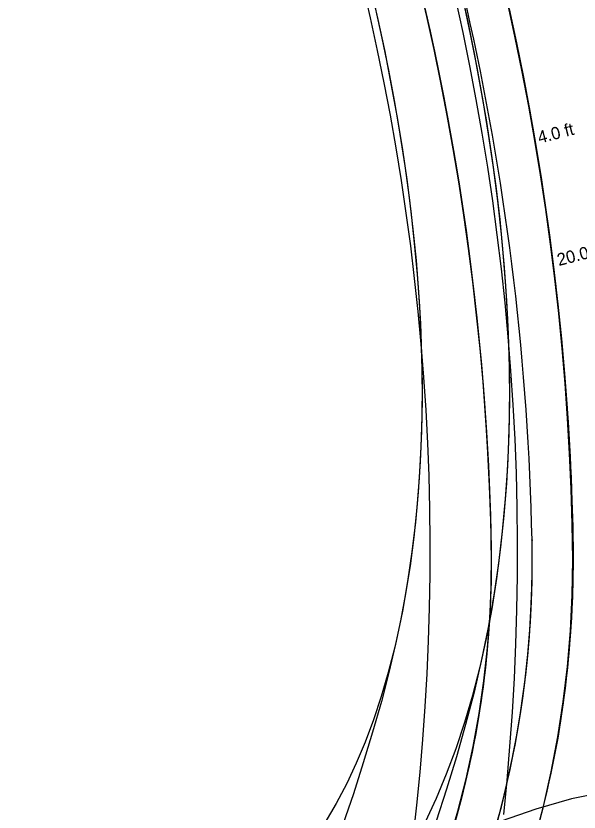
# Model space of a CAD drawing. Extents: x 916040 to 917457, y 328936 to 330267.
# Drawn here: x 916599.7 to 916654.5, y 329738.6 to 329816 of the extents above; entities that cross this region are included whole.
import ezdxf

# ---------------------------------------------------------------- set-up
doc = ezdxf.new("R2010")
doc.units = 0
for name, color, linetype in [('EB_LeftontoManchester_WB67', 7, 'Continuous'), ('EB_LeftontoManchester_WB67_v2', 7, 'Continuous'), ('NB_ThruontoManchester_WB67', 7, 'Continuous'), ('SB_LeftontoRoute25_WB67', 7, 'Continuous'), ('SB_RightontoRoute25_WB67_v2', 7, 'Continuous'), ('SB_ThruontonSacoRd_WB67', 7, 'Continuous'), ('SU_IntoDriveway', 7, 'Continuous'), ('WB_LeftontoSaco_WB67', 7, 'Continuous'), ('WB_RightontoManchester_WB67', 7, 'Continuous')]:
    doc.layers.add(name, color=color, linetype=linetype)

msp = doc.modelspace()

# ---------------------------------------------------------------- linework, layer by layer
at = {"layer": 'EB_LeftontoManchester_WB67'}
msp.add_arc((916291.649, 329706.552), 388, 12.26429, 55.55708, dxfattribs=at)
at = {"layer": 'EB_LeftontoManchester_WB67_v2'}
msp.add_arc((916291.649, 329706.552), 388, 12.26429, 55.55708, dxfattribs=at)
at = {"layer": 'NB_ThruontoManchester_WB67'}
msp.add_arc((916291.649, 329706.552), 388, 11.6689, 55.55708, dxfattribs=at)
at = {"layer": 'SB_LeftontoRoute25_WB67'}
for points in [[(916634.227, 329818.8), (916634.934, 329815.67), (916635.596, 329812.544), (916636.209, 329809.423), (916636.773, 329806.308), (916637.284, 329803.201), (916637.74, 329800.101), (916638.14, 329797.009), (916638.481, 329793.927), (916638.761, 329790.855), (916638.978, 329787.794), (916639.13, 329784.744), (916639.215, 329781.707), (916639.233, 329778.672), (916639.181, 329775.66), (916639.057, 329772.672), (916638.86, 329769.712), (916638.59, 329766.782), (916638.245, 329763.882), (916637.824, 329761.016), (916637.318, 329758.133), (916636.722, 329755.223), (916636.038, 329752.29), (916635.271, 329749.337), (916634.427, 329746.365), (916633.516, 329743.378), (916632.546, 329740.379), (916631.531, 329737.37)], [(916639.282, 329817.724), (916640.011, 329814.521), (916640.699, 329811.309), (916641.345, 329808.089), (916641.949, 329804.861), (916642.512, 329801.625), (916643.033, 329798.382), (916643.512, 329795.133), (916643.949, 329791.879), (916644.344, 329788.619), (916644.697, 329785.354), (916645.008, 329782.084), (916645.276, 329778.812), (916645.503, 329775.536), (916645.687, 329772.257), (916645.828, 329768.976), (916645.928, 329765.694), (916645.967, 329762.417), (916645.894, 329759.151), (916645.706, 329755.899), (916645.404, 329752.662), (916644.99, 329749.444), (916644.463, 329746.247), (916643.825, 329743.075), (916643.077, 329739.931), (916642.219, 329736.817)], [(916643.236, 329817.493), (916643.923, 329814.251), (916644.56, 329811.007), (916645.148, 329807.763), (916645.681, 329804.518), (916646.159, 329801.274), (916646.579, 329798.03), (916646.937, 329794.789), (916647.232, 329791.551), (916647.461, 329788.316), (916647.623, 329785.086), (916647.714, 329781.863), (916647.733, 329778.634), (916647.677, 329775.421), (916647.545, 329772.227), (916647.335, 329769.053), (916647.045, 329765.902), (916646.673, 329762.776), (916646.218, 329759.676), (916645.67, 329756.556), (916645.027, 329753.415), (916644.293, 329750.264), (916643.475, 329747.113), (916642.582, 329743.968), (916641.626, 329740.833), (916640.618, 329737.713)], [(916647.705, 329816.696), (916648.42, 329813.387), (916649.092, 329810.068), (916649.721, 329806.741), (916650.307, 329803.406), (916650.85, 329800.064), (916651.35, 329796.714), (916651.807, 329793.359), (916652.22, 329789.998), (916652.59, 329786.632), (916652.917, 329783.261), (916653.2, 329779.886), (916653.439, 329776.508), (916653.635, 329773.127), (916653.787, 329769.744), (916653.896, 329766.359), (916653.943, 329762.946), (916653.877, 329759.513), (916653.693, 329756.076), (916653.391, 329752.64), (916652.971, 329749.21), (916652.433, 329745.792), (916651.776, 329742.391), (916651.003, 329739.01), (916650.113, 329735.655)]]:
    msp.add_lwpolyline(points, dxfattribs=at)
msp.add_circle((916649.935, 329765.025), 0.0417, dxfattribs=at)
msp.add_circle((916649.935, 329765.025), 0.0417, dxfattribs=at)
for centre, radius, start, end in [((916391.491, 329759.636), 258.5, 1.1947, 23.66768), ((916553.456, 329763.013), 96.5, 331.95112, 1.1947)]:
    msp.add_arc(centre, radius, start, end, dxfattribs=at)
at = {"layer": 'SB_RightontoRoute25_WB67_v2'}
for points in [[(916638.979, 329819.002), (916639.724, 329815.803), (916640.429, 329812.595), (916641.091, 329809.378), (916641.712, 329806.153), (916642.292, 329802.92), (916642.83, 329799.68), (916643.325, 329796.434), (916643.779, 329793.181), (916644.191, 329789.923), (916644.561, 329786.66), (916644.889, 329783.393), (916645.174, 329780.121), (916645.417, 329776.846), (916645.618, 329773.569), (916645.777, 329770.289), (916645.893, 329767.007), (916645.964, 329763.73), (916645.937, 329760.472), (916645.796, 329757.227), (916645.542, 329753.995), (916645.176, 329750.781), (916644.698, 329747.587), (916644.108, 329744.416), (916643.41, 329741.271), (916642.602, 329738.156)], [(916642.94, 329818.83), (916643.643, 329815.6), (916644.299, 329812.369), (916644.905, 329809.137), (916645.46, 329805.905), (916645.96, 329802.673), (916646.404, 329799.441), (916646.788, 329796.211), (916647.11, 329792.983), (916647.368, 329789.759), (916647.559, 329786.539), (916647.682, 329783.325), (916647.734, 329780.117), (916647.713, 329776.918), (916647.618, 329773.729), (916647.447, 329770.554), (916647.201, 329767.419), (916646.88, 329764.339), (916646.485, 329761.32), (916646.014, 329758.366), (916645.467, 329755.482), (916644.844, 329752.673), (916644.145, 329749.943), (916643.369, 329747.297), (916642.518, 329744.739), (916641.593, 329742.273), (916640.597, 329739.903), (916639.522, 329737.613)], [(916647.408, 329818.017), (916648.139, 329814.712), (916648.828, 329811.397), (916649.475, 329808.073), (916650.078, 329804.741), (916650.638, 329801.401), (916651.155, 329798.055), (916651.629, 329794.702), (916652.06, 329791.343), (916652.447, 329787.979), (916652.791, 329784.61), (916653.092, 329781.237), (916653.349, 329777.86), (916653.562, 329774.48), (916653.732, 329771.098), (916653.858, 329767.713), (916653.937, 329764.321), (916653.918, 329760.904), (916653.783, 329757.48), (916653.53, 329754.056), (916653.16, 329750.636), (916652.673, 329747.226), (916652.069, 329743.83), (916651.348, 329740.452), (916650.511, 329737.099)], [(916634.648, 329816.96), (916635.326, 329813.844), (916635.958, 329810.733), (916636.54, 329807.627), (916637.072, 329804.528), (916637.551, 329801.437), (916637.973, 329798.353), (916638.339, 329795.278), (916638.645, 329792.213), (916638.889, 329789.158), (916639.069, 329786.115), (916639.185, 329783.084), (916639.234, 329780.065), (916639.214, 329777.062), (916639.125, 329774.073), (916638.965, 329771.104), (916638.735, 329768.18), (916638.437, 329765.319), (916638.071, 329762.528), (916637.638, 329759.813), (916637.139, 329757.18), (916636.573, 329754.634), (916635.944, 329752.179), (916635.252, 329749.819), (916634.499, 329747.557), (916633.688, 329745.397), (916632.823, 329743.34), (916631.898, 329741.373), (916630.886, 329739.441), (916629.779, 329737.54)]]:
    msp.add_lwpolyline(points, dxfattribs=at)
msp.add_circle((916649.935, 329765.025), 0.0417, dxfattribs=at)
msp.add_circle((916649.935, 329765.025), 0.0417, dxfattribs=at)
for centre, radius, start, end in [((916391.491, 329759.636), 258.5, 1.1947, 23.66768), ((916553.456, 329763.013), 96.5, 325.71916, 1.1947)]:
    msp.add_arc(centre, radius, start, end, dxfattribs=at)
at = {"layer": 'SB_ThruontonSacoRd_WB67'}
for points in [[(916638.369, 329736.081), (916638.728, 329739.269), (916639.045, 329742.46), (916639.317, 329745.653), (916639.546, 329748.85), (916639.732, 329752.05), (916639.873, 329755.252), (916639.97, 329758.455), (916640.022, 329761.66), (916640.031, 329764.865), (916639.995, 329768.071), (916639.915, 329771.276), (916639.791, 329774.48), (916639.623, 329777.683), (916639.411, 329780.884), (916639.155, 329784.082), (916638.856, 329787.276), (916638.513, 329790.467), (916638.127, 329793.654), (916637.698, 329796.835), (916637.225, 329800.011), (916636.71, 329803.183), (916636.152, 329806.349), (916635.552, 329809.51), (916634.909, 329812.664), (916634.225, 329815.813), (916633.5, 329818.954)], [(916641.807, 329735.555), (916642.722, 329738.674), (916643.526, 329741.817), (916644.217, 329744.982), (916644.796, 329748.163), (916645.262, 329751.36), (916645.616, 329754.567), (916645.857, 329757.782), (916645.986, 329761.001), (916646.002, 329764.22), (916645.919, 329767.446), (916645.791, 329770.681), (916645.623, 329773.922), (916645.415, 329777.167), (916645.166, 329780.413), (916644.876, 329783.66), (916644.545, 329786.907), (916644.172, 329790.153), (916643.758, 329793.396), (916643.302, 329796.636), (916642.804, 329799.871), (916642.265, 329803.101), (916641.684, 329806.326), (916641.061, 329809.544), (916640.397, 329812.754), (916639.692, 329815.957), (916638.945, 329819.151)], [(916647.18, 329738.368), (916647.508, 329741.673), (916647.791, 329744.982), (916648.028, 329748.295), (916648.22, 329751.611), (916648.367, 329754.93), (916648.467, 329758.251), (916648.522, 329761.573), (916648.531, 329764.896), (916648.494, 329768.218), (916648.411, 329771.541), (916648.282, 329774.862), (916648.108, 329778.181), (916647.888, 329781.497), (916647.624, 329784.811), (916647.313, 329788.121), (916646.958, 329791.427), (916646.559, 329794.727), (916646.114, 329798.023), (916645.625, 329801.312), (916645.092, 329804.596), (916644.514, 329807.874), (916643.893, 329811.146), (916643.228, 329814.41), (916642.521, 329817.666)], [(916650.178, 329735.804), (916651.049, 329739.137), (916651.807, 329742.504), (916652.45, 329745.899), (916652.977, 329749.318), (916653.387, 329752.757), (916653.679, 329756.211), (916653.852, 329759.675), (916653.905, 329763.145), (916653.852, 329766.597), (916653.746, 329770.029), (916653.594, 329773.452), (916653.397, 329776.867), (916653.154, 329780.274), (916652.866, 329783.672), (916652.535, 329787.063), (916652.159, 329790.446), (916651.739, 329793.821), (916651.276, 329797.189), (916650.769, 329800.548), (916650.219, 329803.898), (916649.626, 329807.24), (916648.99, 329810.573), (916648.31, 329813.896), (916647.588, 329817.21)]]:
    msp.add_lwpolyline(points, dxfattribs=at)
msp.add_circle((916649.935, 329765.025), 0.0417, dxfattribs=at)
msp.add_circle((916649.935, 329765.025), 0.0417, dxfattribs=at)
for centre, radius, start, end in [((916391.491, 329759.636), 258.5, 1.1947, 23.66768), ((916553.456, 329763.013), 96.5, 323.65465, 1.1947)]:
    msp.add_arc(centre, radius, start, end, dxfattribs=at)
at = {"layer": 'WB_LeftontoSaco_WB67'}
msp.add_lwpolyline([(916681.983, 329737.873), (916678.63, 329739.073), (916675.182, 329740.014), (916671.662, 329740.687), (916668.091, 329741.086), (916664.494, 329741.206), (916660.892, 329741.044), (916657.31, 329740.6), (916653.769, 329739.876), (916650.301, 329738.882), (916646.922, 329737.696)], dxfattribs=at)
at = {"layer": 'WB_RightontoManchester_WB67'}
msp.add_arc((916291.649, 329706.552), 384, 12.55823, 55.55708, dxfattribs=at)

# ---------------------------------------------------------------- texts
at = {"layer": 'SU_IntoDriveway'}
for s, p in [('4.0 ft', (916650.658, 329803.591)), ('20.0 ft', (916652.547, 329791.686))]:
    msp.add_text(s, height=1.2, rotation=14.45691, dxfattribs=at).set_placement(p)

doc.saveas('drawing.dxf')
